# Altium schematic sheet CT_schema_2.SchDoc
size 401 x 230 mm
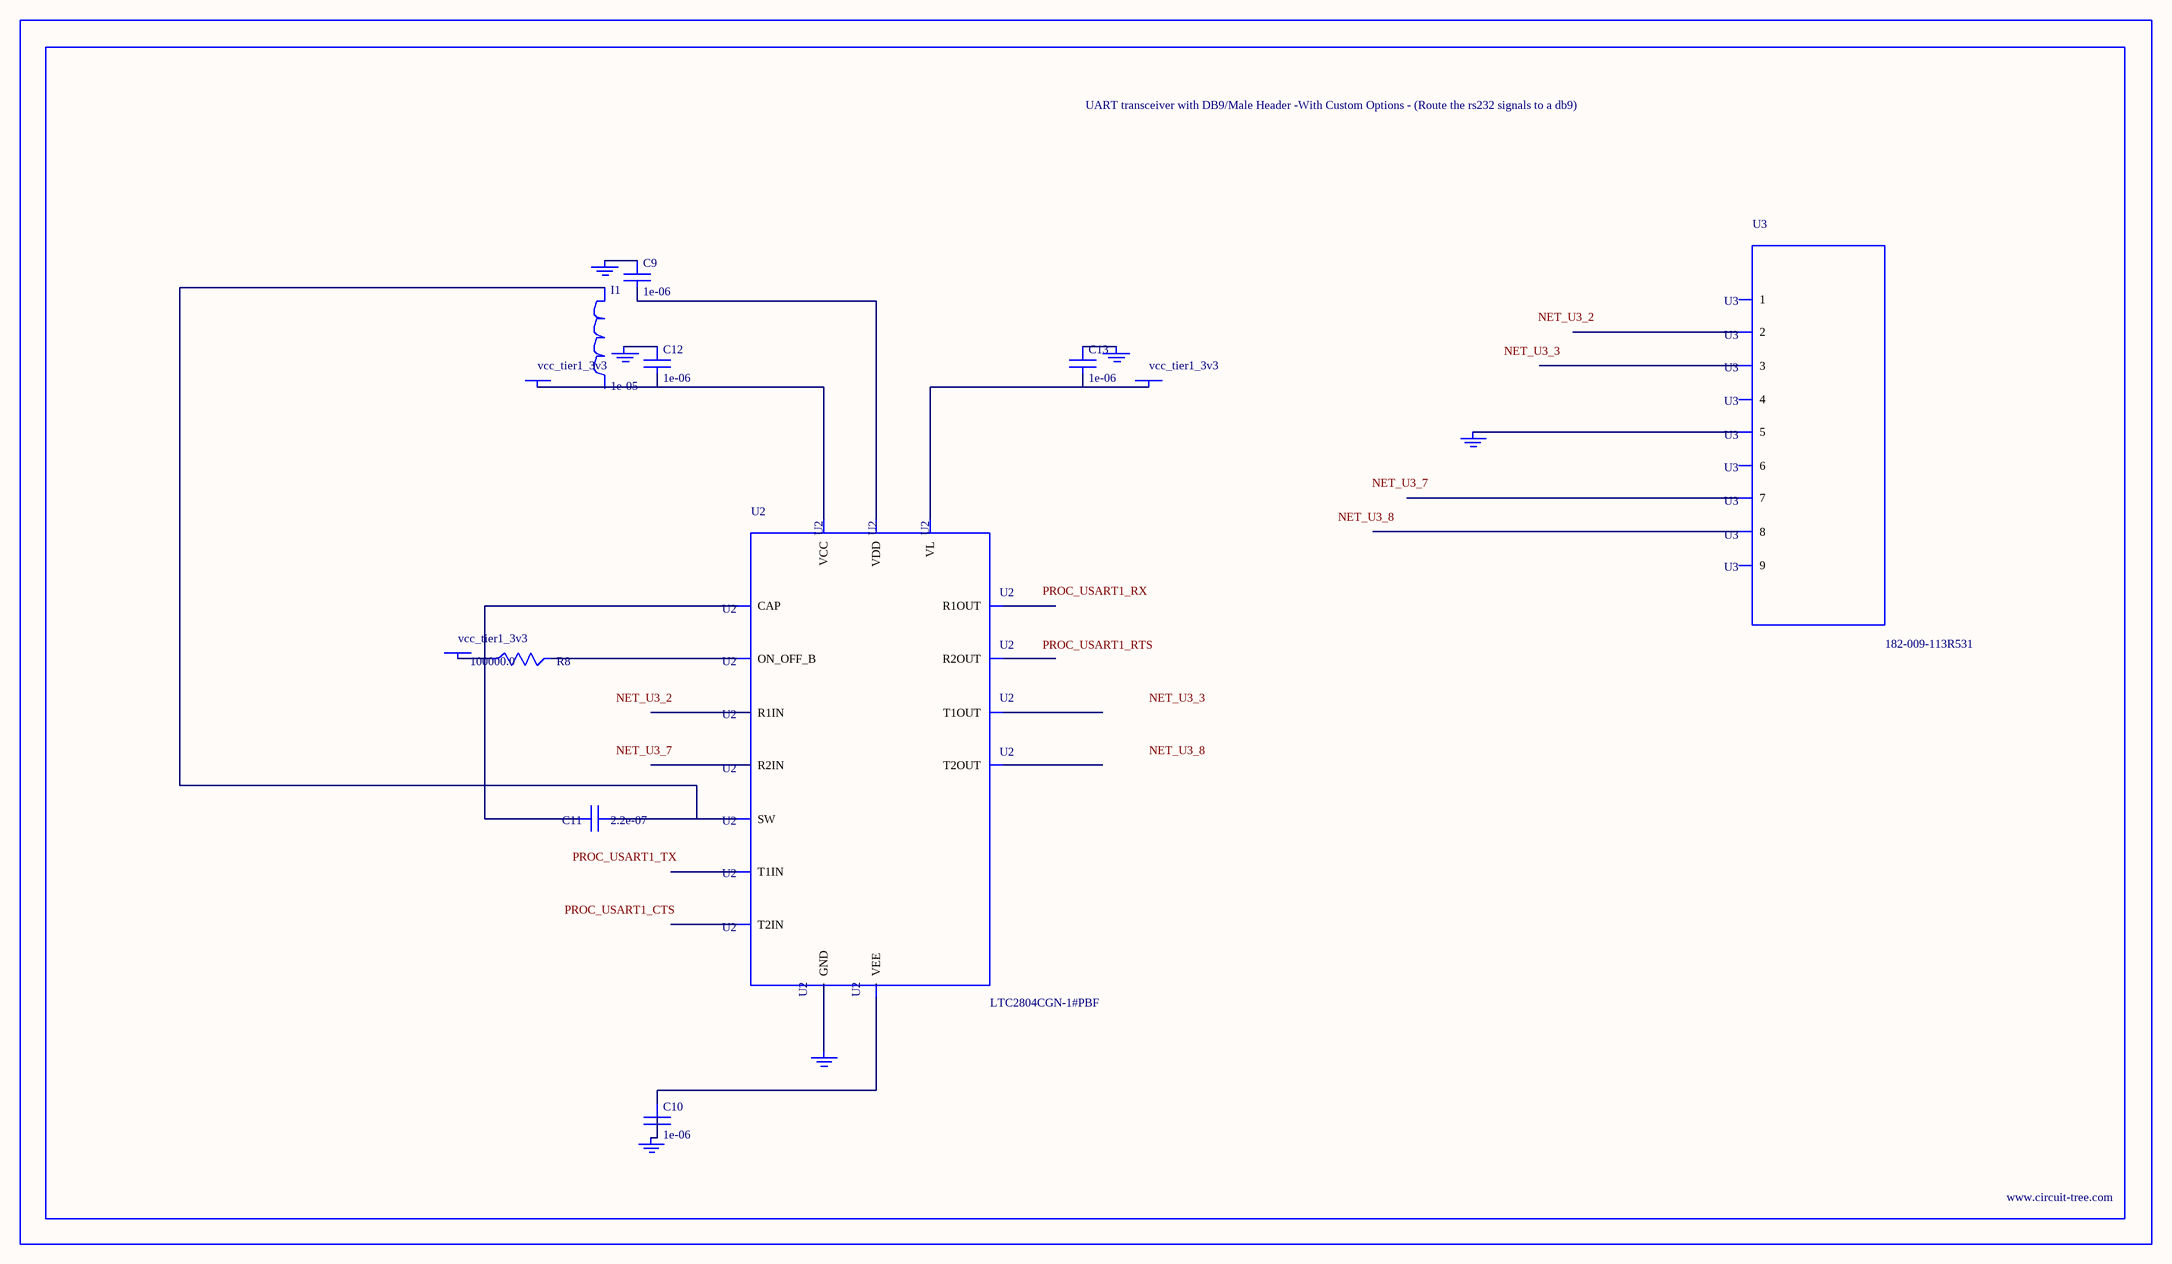
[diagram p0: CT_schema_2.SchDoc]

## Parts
BORDER1  (no value)
C9  1e-06  [C0603]
C10  1e-06  [C0603]
C11  2.2e-07  [C0603]
C12  1e-06  [C0603]
C13  1e-06  [C0603]
GND_INSTANCE_1_0  (no value)
GND_INSTANCE_1_1  (no value)
GND_INSTANCE_1_2  (no value)
GND_INSTANCE_1_3  (no value)
GND_INSTANCE_1_4  (no value)
GND_INSTANCE_1_5  (no value)
I1  1e-05  [L1210]
POWER_INSTANCE_1_0  vcc_tier1_3v3
POWER_INSTANCE_1_1  vcc_tier1_3v3
POWER_INSTANCE_1_2  vcc_tier1_3v3
R8  100000.0  [R0603]
U2  LTC2804CGN-1#PBF  [SSOP-16]
U3  182-009-113R531  [182-009-MALE]

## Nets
NetC9_1: C9.1 GND_INSTANCE_1_1.0(GND)
NetC9_2: C9.2 U2.6(VDD)
NetC10_1: C10.1 U2.9(VEE)
NetC10_2: C10.2 GND_INSTANCE_1_2.0(GND)
NetC11_1: C11.1 I1.1 U2.7(SW)
NetC11_2: C11.2 U2.10(CAP)
NetC12_1: C12.1 GND_INSTANCE_1_0.0(GND)
NetC12_2: C12.2 POWER_INSTANCE_1_0.0(PWR) U2.5(VCC)
NetC13_1: C13.1 GND_INSTANCE_1_3.0(GND)
NetC13_2: C13.2 POWER_INSTANCE_1_2.0(PWR) U2.12(VL)
NetGND_INSTANCE_1_4_0: GND_INSTANCE_1_4.0(GND) U2.8(GND)
NetGND_INSTANCE_1_5_0: GND_INSTANCE_1_5.0(GND) U3.5
NetPOWER_INSTANCE_1_1_0: POWER_INSTANCE_1_1.0(PWR) R8.1
NetR8_2: R8.2 U2.11(ON_OFF_B)

Not connected (* = marked no-connect by the designer): I1 2; U2 1(R1IN) 2(R2IN) 3(T1OUT) 4(T2OUT) 13(T2IN) 14(T1IN) 15(R2OUT) 16(R1OUT); U3 1 2 3 4 6 7 8 9

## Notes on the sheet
- Labels drawn without touching a wire or pin: NET_U3_2, NET_U3_3, NET_U3_7, NET_U3_8, PROC_USART1_CTS, PROC_USART1_RTS, PROC_USART1_RX, PROC_USART1_TX

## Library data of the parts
BORDER1 = BORDER_PAGE1
C9 C10 C12 C13 = C0603C105K3RACTU
C11 = C0603C224K3RAC
GND_INSTANCE_1_0-GND_INSTANCE_1_5 = GND
I1 = CBC3225T100MR
POWER_INSTANCE_1_0-POWER_INSTANCE_1_2 = PWR
R8 = RC0603JR-07100KL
